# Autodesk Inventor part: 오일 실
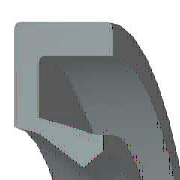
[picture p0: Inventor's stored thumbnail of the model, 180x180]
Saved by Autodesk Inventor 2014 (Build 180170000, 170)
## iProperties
IsCustomPart: 1
Created: 2012-02
Part Number: 오일 실
Material: 고무
Description: 오일 실 - 스프링 장착, 비스프링, 고무 덮개 G
Document SubType Name: Modeling
Standard: JIS B 2402
Designer: mduedu
Standards Organization: JIS
Language: ko-KR
Size Designation: 20 32 5 A
Categories: <MemberInstance><Categories><Category DisplayName="샤프트 부품" InternalName="7f7aeb1f-a693-4053-b835-cee3144e0d98" Mnemonic="SHFT"><Category DisplayName="실링" Intern
Density: 0.93 g/cm^3
Appearance: Rubber - Black - Version 1.1
Author: mduedu
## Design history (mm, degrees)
body "Solid1"
revolve "회전1" stored, may be unused: angle "d29" = 360 deg
chamfer "모따기1" distance "d30" = 0.25 (= 0.05 x b); stored, may be unused: second distance "d31" = 0.5 (= 0.1 x b), angle "d39" = 45 deg
chamfer "모따기2" distance "d32" = 0.5 (= 0.1 x b); stored, may be unused: second distance "d33" = 0.25 (= 0.05 x b), angle "d40" = 45 deg
fillet "모깎기1" dims "d34" = 0.25 (= 0.05 x b)
sketch "스케치2"
  geometry: L1 (10.997, -3.438)-(11.297, -5); L2 (10.597, -3.282)-(10.997, -3.438); L3 (10, -1.72)-(10.597, -3.282); L4 (11.091, -1.22)-(10, -1.72); L5 (12.133, -3.75)-(11.091, -1.22); L6 (13.333, -3.75)-(12.133, -3.75); L7 (14.667, -1.25)-(13.333, -3.75); L8 (14.667, 0)-(14.667, -1.25); L9 (16, 0)-(14.667, 0); L10 (16, -5)-(16, 0); L11 (11.297, -5)-(16, -5); L12 (0, -9.6)-(0, 1.6) reference; L13 (28, 0)-(14, 0) reference
  constraints: 22 end point, 3 horizontal, 2 vertical
  dimensions: "d2" = 5 distance of L10.start L9.start (= b); "d4" = 1.25 vertical distance of L5.start L1.end (= 0.25 x b); "d6" = 1.33333 distance of L9.start L8.start (= 0.111111 x dd - 0.111111 x Diam); "d8" = 1.25 distance of L8.start L7.start (= 0.25 x b); "d10" = 1.33333 horizontal distance of L7.start L6.start (= 0.111111 x dd - 0.111111 x Diam); "d12" = 1.21951 vertical distance of L9.start L4.start (= 0.243902 x b); "d14" = 1.09091 horizontal distance of L4.start L3.start (= 0.0909091 x dd - 0.0909091 x Diam); "d16" = 0.5 vertical distance of L4.start L3.start (= 0.1 x b); "d18" = 1.2 distance of L6.start L5.start (= 0.1 x dd - 0.1 x Diam); "d20" = 1.5625 vertical distance of L3.start L2.start (= 0.3125 x b); "d22" = 0.59701 horizontal distance of L3.start L2.start (= 0.0497512 x dd - 0.0497512 x Diam); "d24" = 0.3 horizontal distance of L1.start L1.end (= 0.025 x dd - 0.025 x Diam); "d26" = 1.5625 vertical distance of L1.start L1.end (= 0.3125 x b); "d28" = 0.4 horizontal distance of L2.start L1.start (= 0.0333333 x dd - 0.0333333 x Diam); "d35" = 0 distance between parallel lines of L13 L9; "d36" = 16 distance between parallel lines of L12 L10 (= 0.5 x dd); "d37" = 10 distance from line of L12 L3.start (= 0.5 x Diam)
other parameters: "dd" = 32 [user parameter; used in 8 equation terms], "b" = 5 [user parameter; used in 12 equation terms], "d1" = 8 (derived), "d3" = 2 (derived), "d5" = 2.22222 (derived), "d7" = 2 (derived), "d9" = 2.22222 (derived), "d11" = 1.95122 (derived), "d13" = 1.81818 (derived), "d15" = 0.8 (derived), "d17" = 2 (derived), "d19" = 2.5 (derived), "d21" = 0.99502 (derived), "d23" = 0.5 (derived), "d25" = 2.5 (derived), "d27" = 0.66667 (derived), "d38" = 0
